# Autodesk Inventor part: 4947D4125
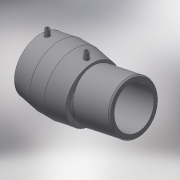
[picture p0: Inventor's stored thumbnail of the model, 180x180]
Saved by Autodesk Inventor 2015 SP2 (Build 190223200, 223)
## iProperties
Created: 2017-06
Part Number: 4947D4125
Material: Generic
Description: PLASSON ADJUSTABLE ELBOW (ONE SIDE) 125
Document SubType Name: Modeling
Designer: KIM
Mass: 55.0731 g
Surface Area: 148.067 cm^2
Volume: 55.0731 cm^3
Density: 1 g/cm^3
Appearance: Default
Author: KIM
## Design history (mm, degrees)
derived "4947D4.ipt"
feature "Solid1::4947D4.ipt"
tag "TaggingFeature1"
body "Solid1"
other parameters: "d0" = 153.3, "d2" = 157, "d4" = 45, "d5" = 141.3, "d7" = 125, "d8" = 168 deg, "d10" = 36, "d11" = 12, "d29" = 95, "d30" = 15, "d31" = 58.4, "d34" = 5 deg, "d41" = 4, "d42" = 14, "d43" = 0, "d48" = 112.5, "d55" = 37.98, "d57" = 168 deg, "d62" = 3, "d63" = 0, "d65" = 292, "d66" = 125, "d67" = 112.5, "d68" = 135 deg, "d70" = 58.09, "d71" = 3.14, "d_" = 125, "L_" = 292, "D_" = 157, "A_" = 95, "d_2" = 12, "L_0" = 148, "D_1" = 125, "d54" = 63.3, "d59" = 177.35893
